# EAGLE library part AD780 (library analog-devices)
High Precision Reference 2.5V/3.0V Source: http://www.analog.com/UploadedFiles/Data_Sheets/AD780.pdf
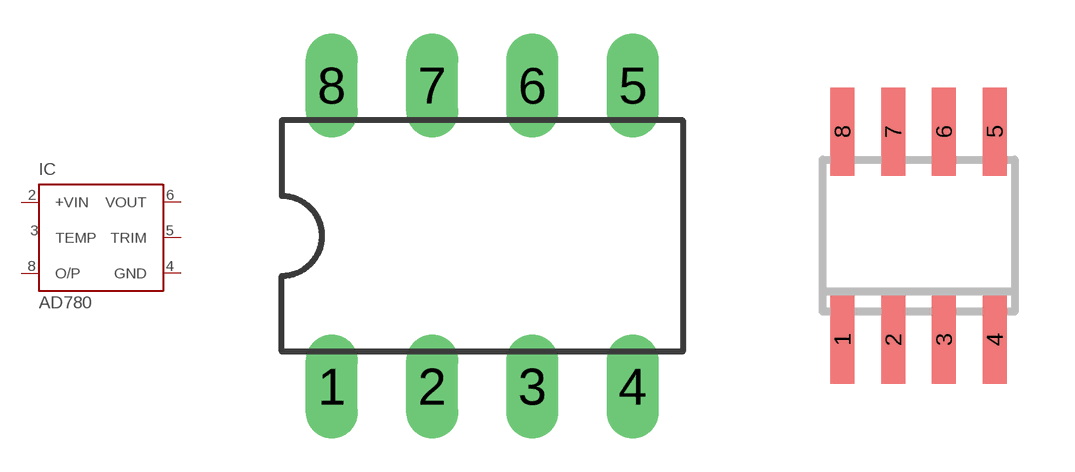
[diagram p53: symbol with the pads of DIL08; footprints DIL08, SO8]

Designator prefix IC

## AD780N (MF: ALTERA CORPORATION; MPN: AD780ANZ; OC_FARNELL: 9605550; OC_NEWARK: 59K5478)  [DIL08]
2  +VIN  in
3  TEMP  in
4  GND  pwr
5  TRIM  in
6  VOUT  in
8  O/P  pas

## AD780R (MPN: AD780BRZ-REEL; OC_FARNELL: 1464655; OC_NEWARK: 12M8938)  [SO8]
Pads as for DIL08

## Footprint DIL08 (pad centres in mm)
Dual In Line Package
drill 0.813 long: 1 -3.81,-3.81; 2 -1.27,-3.81; 3 1.27,-3.81; 4 3.81,-3.81; 5 3.81,3.81; 6 1.27,3.81; 7 -1.27,3.81; 8 -3.81,3.81

## Footprint SO8 (pad centres in mm)
8-Lead Small Outline IC (SO-8) Source: http://www.analog.com/UploadedFiles/Data_Sheets/703465986AD8611_2_0.pdf
smd 0.6 x 2.2: 1 -1.905,-2.6; 2 -0.635,-2.6; 3 0.635,-2.6; 4 1.905,-2.6; 5 1.905,2.6; 6 0.635,2.6; 7 -0.635,2.6; 8 -1.905,2.6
